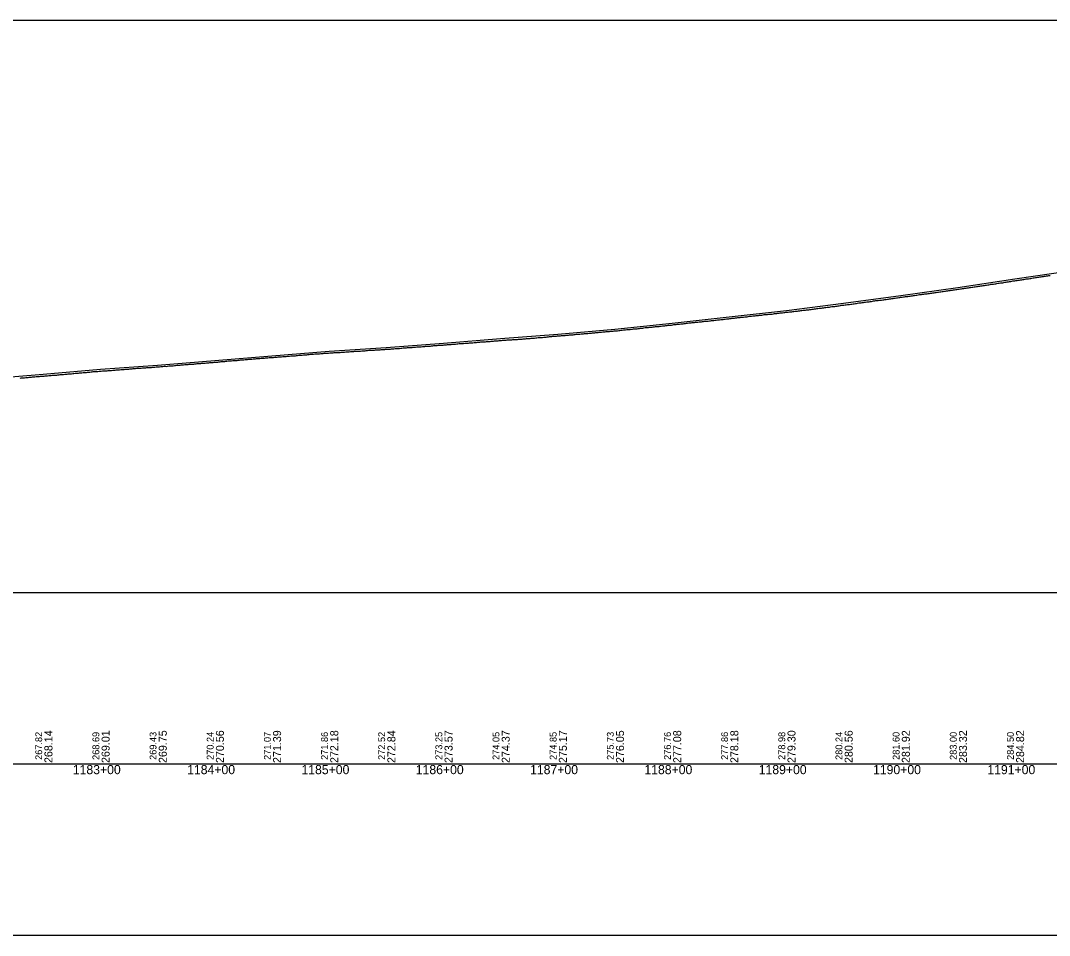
# Model space of a CAD drawing. Extents: x 2898 to 49495, y -15038 to -13538.
# Drawn here: x 7583 to 8483, y -15038 to -14238 of the extents above; entities that cross this region are included whole.
import ezdxf

# ---------------------------------------------------------------- set-up
doc = ezdxf.new("R2010")
doc.units = 0
for name, color, linetype in [('RD_DDB_Profile_EX', 7, 'Continuous'), ('RD_DDB_Profile_PR', 7, 'Continuous'), ('RD_DDB_StaTX', 7, 'Continuous'), ('RD_DDB_StripGrade', 7, 'Continuous'), ('RD_GPK_Profile_Cell', 7, 'Continuous'), ('RD_SHT_ShtClip', 7, 'Continuous')]:
    doc.layers.add(name, color=color, linetype=linetype)

msp = doc.modelspace()

# ---------------------------------------------------------------- linework, layer by layer
at = {"layer": 'RD_DDB_Profile_EX'}
for points in [[(8445.6, -14467.23), (8446.6, -14467), (8447.6, -14466.91), (8448.59, -14466.7), (8449.6, -14466.56), (8450.6, -14466.37), (8451.6, -14466.15), (8452.22, -14466.1), (8453.23, -14466.02), (8454.23, -14465.77), (8455.23, -14465.67), (8456.23, -14465.5), (8457.22, -14465.36), (8458.23, -14465.18), (8459.23, -14465.06), (8460.23, -14464.89), (8461.23, -14464.79), (8462.23, -14464.67), (8463.23, -14464.44), (8464.23, -14464.28), (8465.23, -14464.16), (8466.23, -14464.01), (8467.23, -14463.88), (8468.23, -14463.72), (8469.23, -14463.55), (8470.23, -14463.4), (8471.23, -14463.14), (8472.23, -14463.04), (8473.23, -14462.96), (8474.23, -14462.84), (8475.23, -14462.66), (8476.23, -14462.54), (8477.24, -14462.26), (8478.23, -14462.15), (8479.02, -14462.01), (8480.01, -14461.91), (8481.02, -14461.81), (8482.02, -14461.58), (8483.01, -14461.51), (8484.02, -14461.34)], [(8345.61, -14481.55), (8346.77, -14481.41), (8347.77, -14481.22), (8348.61, -14481.1), (8349.61, -14480.98), (8350.61, -14480.88), (8351.78, -14480.65), (8352.61, -14480.56), (8353.61, -14480.42), (8354.61, -14480.37), (8355.78, -14480.15), (8356.61, -14480.02), (8357.61, -14479.87), (8358.78, -14479.69), (8359.61, -14479.61), (8360.61, -14479.5), (8361.61, -14479.36), (8362.61, -14479.25), (8363.61, -14479.1), (8364.6, -14478.95), (8365.61, -14478.85), (8366.79, -14478.62), (8367.6, -14478.5), (8368.61, -14478.3), (8369.78, -14478.13), (8370.6, -14477.97), (8371.61, -14477.9), (8372.6, -14477.79), (8373.55, -14477.69), (8374.54, -14477.53), (8375.55, -14477.38), (8376.54, -14477.32), (8377.54, -14477.08), (8378.55, -14477.01), (8379.54, -14476.9), (8380.55, -14476.75), (8381.54, -14476.57), (8382.54, -14476.42), (8383.55, -14476.31), (8384.54, -14476.16), (8385.55, -14476.05), (8386.57, -14475.9), (8387.57, -14475.8), (8388.57, -14475.6), (8389.57, -14475.41), (8390.57, -14475.3), (8391.57, -14475.2), (8392.57, -14475.01), (8393.57, -14474.85), (8394.57, -14474.7), (8395.57, -14474.56), (8396.57, -14474.5), (8397.57, -14474.28), (8398.57, -14474.18), (8399.57, -14474.05), (8400.57, -14473.82), (8401.57, -14473.72), (8402.57, -14473.56), (8403.57, -14473.45), (8404.57, -14473.34), (8405.57, -14473.15), (8406.57, -14472.97), (8407.57, -14472.79), (8408.57, -14472.64), (8409.57, -14472.49), (8410.57, -14472.39), (8411.57, -14472.19), (8412.57, -14472.08), (8413.57, -14471.94), (8414.57, -14471.75), (8415.57, -14471.59), (8416.57, -14471.49), (8417.57, -14471.29), (8418.57, -14471.2), (8419.57, -14471.06), (8420.57, -14470.95), (8421.57, -14470.8), (8422.57, -14470.61), (8423.57, -14470.47), (8424.57, -14470.33), (8425.57, -14470.18), (8426.57, -14470.04), (8427.57, -14469.95), (8428.57, -14469.81), (8429.57, -14469.62), (8430.57, -14469.42), (8431.59, -14469.25), (8432.6, -14469.08), (8433.59, -14468.96), (8434.6, -14468.86), (8435.6, -14468.75), (8436.59, -14468.61), (8437.6, -14468.28), (8438.59, -14468.2), (8439.6, -14468.04), (8440.6, -14467.89), (8441.59, -14467.76), (8442.6, -14467.66), (8443.59, -14467.44), (8444.59, -14467.33), (8445.6, -14467.23)], [(8246.04, -14494.32), (8247.04, -14494.18), (8248.04, -14494.12), (8249.04, -14494.02), (8250.04, -14493.96), (8251.04, -14493.87), (8252.04, -14493.77), (8253.04, -14493.58), (8254.04, -14493.48), (8255.04, -14493.37), (8256.04, -14493.27), (8257.04, -14493.22), (8258.04, -14493.12), (8259.05, -14493.01), (8260.04, -14492.82), (8261.04, -14492.63), (8262.04, -14492.62), (8263.04, -14492.57), (8264.04, -14492.38), (8265.04, -14492.23), (8266.04, -14492.08), (8267.05, -14491.98), (8268.04, -14491.83), (8269.04, -14491.78), (8270.04, -14491.63), (8271.04, -14491.53), (8272.05, -14491.42), (8273.04, -14491.28), (8274.04, -14491.13), (8275.05, -14491.02), (8276.04, -14490.83), (8277.04, -14490.69), (8278.04, -14490.59), (8279.04, -14490.53), (8280.04, -14490.34), (8281.04, -14490.24), (8282.04, -14490.09), (8283.05, -14489.99), (8284.04, -14489.88), (8285.04, -14489.73), (8286.04, -14489.59), (8287.04, -14489.48), (8288.05, -14489.33), (8289.04, -14489.18), (8290.04, -14489.03), (8291.05, -14488.94), (8292.04, -14488.82), (8293.04, -14488.63), (8294.03, -14488.53), (8294.71, -14488.42), (8295.71, -14488.36), (8296.72, -14488.18), (8297.71, -14488.12), (8298.72, -14487.87), (8299.71, -14487.82), (8300.71, -14487.67), (8301.72, -14487.47), (8302.71, -14487.36), (8303.72, -14487.22), (8304.71, -14487.16), (8305.72, -14486.92), (8306.72, -14486.77), (8307.71, -14486.7), (8308.72, -14486.6), (8309.71, -14486.41), (8310.72, -14486.31), (8311.72, -14486.16), (8312.72, -14486.05), (8313.72, -14485.95), (8314.71, -14485.75), (8315.72, -14485.56), (8316.72, -14485.42), (8317.72, -14485.35), (8318.72, -14485.21), (8319.72, -14485.1), (8320.72, -14484.95), (8321.72, -14484.81), (8322.72, -14484.7), (8323.72, -14484.54), (8324.72, -14484.39), (8325.72, -14484.29), (8326.73, -14484.24), (8327.72, -14484.01), (8328.73, -14483.76), (8329.72, -14483.66), (8330.72, -14483.56), (8331.73, -14483.37), (8332.72, -14483.25), (8333.73, -14483.1), (8334.72, -14483.01), (8335.73, -14482.9), (8336.73, -14482.83), (8337.72, -14482.63), (8338.73, -14482.58), (8339.61, -14482.4), (8340.61, -14482.27), (8341.77, -14482.08), (8342.61, -14481.99), (8343.61, -14481.85), (8344.77, -14481.71), (8345.61, -14481.55)], [(8146, -14505.35), (8147, -14505.3), (8148.01, -14505.15), (8149, -14505.05), (8150, -14504.91), (8151.01, -14504.81), (8152, -14504.76), (8153, -14504.7), (8154.01, -14504.6), (8155, -14504.31), (8156, -14504.21), (8157.01, -14504.16), (8158, -14504.01), (8159.01, -14503.91), (8160, -14503.81), (8161, -14503.76), (8162.01, -14503.66), (8163, -14503.51), (8164, -14503.46), (8165.01, -14503.31), (8166, -14503.16), (8167, -14503.01), (8168.01, -14502.91), (8169, -14502.81), (8170, -14502.71), (8171.01, -14502.57), (8172, -14502.46), (8173, -14502.36), (8174, -14502.31), (8175, -14502.21), (8176.01, -14502.11), (8177, -14502.01), (8178, -14501.91), (8179.01, -14501.77), (8180, -14501.66), (8181, -14501.47), (8182.01, -14501.42), (8183, -14501.37), (8184, -14501.27), (8185.01, -14501.26), (8186, -14501.11), (8187, -14500.92), (8188.01, -14500.82), (8189, -14500.68), (8190, -14500.62), (8191, -14500.48), (8192, -14500.37), (8193, -14500.28), (8194, -14500.18), (8195, -14500.08), (8196.01, -14499.97), (8197, -14499.83), (8198, -14499.78), (8199.01, -14499.64), (8199.98, -14499.49), (8200.98, -14499.39), (8201.99, -14499.34), (8202.98, -14499.19), (8203.98, -14499.09), (8204.98, -14499.13), (8205.98, -14498.84), (8206.98, -14498.79), (8207.98, -14498.64), (8208.98, -14498.54), (8209.98, -14498.35), (8210.98, -14498.25), (8211.98, -14498.1), (8212.98, -14498), (8213.98, -14497.9), (8215, -14497.84), (8216, -14497.7), (8217, -14497.55), (8218, -14497.45), (8218.99, -14497.4), (8220, -14497.21), (8221, -14497.06), (8221.99, -14496.96), (8223, -14496.86), (8224, -14496.77), (8224.99, -14496.72), (8226, -14496.66), (8226.99, -14496.46), (8227.99, -14496.36), (8229, -14496.22), (8229.99, -14496.12), (8231.07, -14496.06), (8232, -14496.01), (8232.99, -14495.68), (8233.99, -14495.62), (8235, -14495.56), (8235.99, -14495.47), (8236.99, -14495.37), (8237.99, -14495.22), (8238.99, -14495.12), (8239.99, -14495.07), (8240.99, -14495.06), (8241.99, -14494.82), (8243.04, -14494.71), (8244.04, -14494.61), (8245.04, -14494.47), (8246.04, -14494.32)], [(8046.19, -14514.83), (8047.18, -14514.73), (8048.18, -14514.63), (8049.19, -14514.58), (8050.18, -14514.48), (8051.18, -14514.43), (8052.17, -14514.33), (8053.18, -14514.23), (8053.78, -14514.18), (8054.79, -14514.13), (8055.78, -14514.03), (8056.78, -14513.98), (8057.79, -14513.93), (8058.78, -14513.98), (8059.78, -14513.73), (8060.78, -14513.68), (8061.78, -14513.53), (8062.78, -14513.43), (8063.78, -14513.38), (8064.79, -14513.33), (8065.78, -14513.23), (8066.78, -14513.13), (8067.79, -14513.08), (8068.78, -14512.93), (8069.78, -14512.78), (8070.78, -14512.73), (8071.78, -14512.73), (8072.78, -14512.58), (8073.78, -14512.48), (8074.78, -14512.34), (8075.78, -14512.33), (8076.78, -14512.23), (8077.79, -14512.14), (8078.78, -14512.09), (8079.78, -14511.98), (8080.78, -14511.88), (8081.78, -14511.74), (8082.78, -14511.68), (8083.78, -14511.59), (8084.78, -14511.49), (8085.78, -14511.39), (8086.78, -14511.24), (8087.77, -14511.19), (8088.78, -14511.14), (8089.78, -14511.04), (8090.77, -14510.94), (8091.78, -14510.89), (8092.78, -14510.79), (8093.78, -14510.64), (8094.77, -14510.54), (8095.78, -14510.49), (8096.78, -14510.39), (8097.77, -14510.34), (8098.78, -14510.29), (8099.78, -14510.14), (8100.77, -14510.04), (8101.78, -14509.94), (8102.78, -14509.89), (8103.77, -14509.79), (8104.77, -14509.69), (8105.78, -14509.64), (8106.78, -14509.49), (8107.77, -14509.34), (8108.78, -14509.19), (8109.78, -14509.14), (8110.77, -14509.04), (8111.77, -14508.94), (8112.78, -14508.84), (8113.77, -14508.74), (8114.77, -14508.64), (8115.78, -14508.59), (8116.77, -14508.49), (8117.77, -14508.34), (8118.78, -14508.19), (8119.78, -14508.14), (8120.77, -14508.09), (8121.77, -14508.04), (8122.78, -14507.89), (8123.77, -14507.75), (8124.77, -14507.6), (8125.78, -14507.5), (8126.77, -14507.4), (8127.77, -14507.34), (8128.78, -14507.1), (8129.77, -14507), (8130.77, -14506.95), (8131.77, -14506.9), (8132.78, -14506.8), (8134, -14506.6), (8135.01, -14506.5), (8136.02, -14506.5), (8137, -14506.4), (8138.02, -14506.2), (8139.02, -14506.1), (8140.01, -14506), (8141, -14505.95), (8142.01, -14505.85), (8143, -14505.7), (8144, -14505.6), (8145.01, -14505.5), (8146, -14505.35)], [(7946.07, -14522.67), (7947.07, -14522.57), (7948.06, -14522.52), (7949.07, -14522.37), (7950.07, -14522.32), (7951.06, -14522.27), (7952.32, -14522.22), (7953.07, -14522.22), (7954.15, -14522.15), (7955.06, -14522.02), (7956.13, -14521.91), (7957.07, -14521.82), (7958.06, -14521.67), (7959.06, -14521.67), (7960.07, -14521.62), (7961.06, -14521.52), (7962.06, -14521.47), (7963.07, -14521.37), (7964.06, -14521.32), (7965.06, -14521.17), (7966.07, -14521.02), (7967.06, -14520.97), (7968.06, -14520.87), (7969.06, -14520.77), (7970.07, -14520.82), (7971.06, -14520.77), (7972.06, -14520.67), (7973.07, -14520.52), (7974.19, -14520.47), (7975.19, -14520.42), (7976.19, -14520.37), (7977.19, -14520.27), (7978.19, -14520.22), (7979.19, -14520.12), (7980.19, -14520.07), (7981.19, -14519.97), (7982.19, -14519.87), (7983.19, -14519.82), (7984.19, -14519.77), (7985.19, -14519.62), (7986.19, -14519.52), (7987.19, -14519.42), (7988.19, -14519.32), (7989.18, -14519.32), (7990.19, -14519.27), (7991.19, -14519.22), (7992.19, -14519.12), (7993.19, -14519.02), (7994.19, -14518.97), (7995.19, -14518.92), (7996.19, -14518.77), (7997.19, -14518.72), (7998.19, -14518.57), (7999.18, -14518.57), (8000.19, -14518.52), (8001.19, -14518.52), (8002.18, -14518.32), (8003.19, -14518.22), (8004.19, -14518.12), (8005.19, -14518.02), (8006.18, -14518.02), (8007.19, -14517.97), (8008.19, -14517.83), (8009.18, -14517.78), (8010.19, -14517.72), (8011.19, -14517.68), (8012.18, -14517.58), (8013.18, -14517.53), (8014.19, -14517.48), (8015.18, -14517.42), (8016.18, -14517.43), (8017.19, -14517.32), (8018.19, -14517.23), (8019.18, -14517.18), (8020.19, -14517.08), (8021.19, -14516.98), (8022.18, -14516.93), (8023.18, -14516.88), (8024.19, -14516.83), (8025.18, -14516.73), (8026.18, -14516.58), (8027.18, -14516.58), (8028.19, -14516.52), (8029.18, -14516.38), (8030.19, -14516.33), (8031.19, -14516.23), (8032.18, -14516.18), (8033.19, -14516.08), (8034.18, -14516.03), (8035.18, -14515.83), (8036.19, -14515.73), (8037.18, -14515.68), (8038.18, -14515.63), (8039.19, -14515.53), (8040.18, -14515.48), (8041.19, -14515.38), (8042.18, -14515.23), (8043.19, -14515.18), (8044.19, -14515.03), (8045.17, -14514.93), (8046.19, -14514.83)], [(7846.12, -14529.71), (7846.96, -14529.67), (7848.09, -14529.55), (7848.96, -14529.42), (7849.98, -14529.36), (7850.96, -14529.27), (7852.01, -14529.26), (7852.96, -14529.22), (7853.96, -14529.12), (7854.96, -14529.07), (7855.95, -14528.97), (7856.96, -14528.92), (7857.96, -14528.82), (7858.95, -14528.82), (7859.96, -14528.82), (7860.96, -14528.77), (7861.96, -14528.67), (7862.95, -14528.62), (7863.96, -14528.52), (7864.96, -14528.47), (7865.95, -14528.42), (7866.95, -14528.37), (7867.96, -14528.27), (7868.96, -14528.12), (7869.95, -14528.12), (7870.96, -14528.07), (7871.96, -14527.97), (7872.95, -14527.97), (7873.95, -14527.92), (7874.96, -14527.77), (7875.95, -14527.67), (7876.95, -14527.62), (7877.96, -14527.57), (7878.96, -14527.57), (7879.95, -14527.52), (7880.95, -14527.42), (7881.96, -14527.37), (7882.95, -14527.22), (7883.95, -14527.17), (7884.96, -14527.12), (7885.95, -14526.92), (7886.95, -14526.87), (7888.05, -14526.82), (7889.06, -14526.77), (7890.05, -14526.77), (7891.05, -14526.67), (7892.06, -14526.62), (7893.05, -14526.57), (7894.05, -14526.42), (7895.05, -14526.42), (7896.06, -14526.37), (7897.05, -14526.32), (7898.05, -14526.27), (7899.05, -14526.17), (7900.05, -14526.07), (7901.05, -14525.97), (7902.05, -14526.02), (7903.06, -14525.92), (7904.05, -14525.82), (7905.05, -14525.77), (7906.05, -14525.77), (7907.05, -14525.67), (7908.05, -14525.57), (7909.05, -14525.52), (7910.06, -14525.47), (7911.05, -14525.27), (7912.05, -14525.22), (7913.05, -14525.22), (7914.05, -14525.17), (7915.05, -14525.17), (7916.05, -14525.02), (7917.06, -14524.87), (7918.05, -14524.77), (7919.05, -14524.72), (7920.05, -14524.67), (7921.05, -14524.52), (7922.05, -14524.47), (7923.05, -14524.42), (7924.05, -14524.32), (7925.05, -14524.27), (7926.05, -14524.22), (7927.05, -14524.12), (7928.05, -14524.07), (7929.05, -14523.97), (7930.05, -14523.87), (7931.05, -14523.82), (7932.05, -14523.72), (7933.05, -14523.67), (7934.05, -14523.62), (7935.05, -14523.52), (7936.07, -14523.42), (7937.07, -14523.42), (7938.06, -14523.27), (7939.07, -14523.22), (7940.07, -14523.17), (7941.06, -14523.17), (7942.07, -14523.07), (7943.07, -14522.92), (7944.07, -14522.82), (7945.06, -14522.72), (7946.07, -14522.67)], [(7746.07, -14537.8), (7747.07, -14537.65), (7748.07, -14537.64), (7749.07, -14537.55), (7750.07, -14537.49), (7751.07, -14537.44), (7752.07, -14537.44), (7753.07, -14537.29), (7754.07, -14537.2), (7755.06, -14537.14), (7756.07, -14537.04), (7757.07, -14536.8), (7758.07, -14536.75), (7759.07, -14536.7), (7760.07, -14536.55), (7761.07, -14536.54), (7762.06, -14536.45), (7763.07, -14536.3), (7764.07, -14536.29), (7765.07, -14536.15), (7766.07, -14536.05), (7767.07, -14536), (7768.07, -14535.94), (7769.06, -14535.84), (7770.07, -14535.7), (7771.04, -14535.65), (7771.87, -14535.65), (7772.87, -14535.59), (7773.88, -14535.44), (7774.87, -14535.29), (7775.88, -14535.24), (7776.88, -14535.19), (7777.87, -14535.09), (7778.88, -14535.04), (7779.88, -14534.94), (7780.87, -14534.84), (7781.88, -14534.79), (7782.88, -14534.69), (7783.87, -14534.59), (7784.87, -14534.49), (7785.88, -14534.44), (7786.87, -14534.34), (7787.87, -14534.29), (7788.88, -14534.14), (7789.87, -14534.09), (7790.87, -14533.99), (7791.88, -14533.99), (7792.87, -14533.94), (7793.87, -14533.79), (7794.87, -14533.69), (7795.87, -14533.64), (7796.87, -14533.64), (7797.87, -14533.49), (7798.88, -14533.43), (7799.87, -14533.38), (7800.87, -14533.23), (7801.88, -14533.18), (7802.87, -14533.18), (7803.87, -14533.08), (7804.87, -14532.98), (7805.87, -14532.88), (7806.87, -14532.78), (7807.87, -14532.73), (7808.87, -14532.63), (7809.87, -14532.53), (7810.87, -14532.53), (7811.87, -14532.43), (7812.87, -14532.33), (7813.87, -14532.28), (7814.86, -14532.18), (7815.87, -14532.13), (7816.87, -14532.03), (7817.86, -14531.93), (7818.87, -14531.78), (7819.87, -14531.73), (7820.86, -14531.72), (7821.87, -14531.62), (7822.87, -14531.57), (7823.86, -14531.52), (7824.86, -14531.37), (7825.87, -14531.27), (7826.86, -14531.12), (7827.86, -14531.07), (7828.87, -14531.02), (7829.86, -14531.02), (7830.86, -14530.87), (7831.87, -14530.77), (7832.87, -14530.77), (7833.86, -14530.72), (7834.86, -14530.52), (7835.87, -14530.42), (7836.86, -14530.32), (7837.86, -14530.22), (7838.87, -14530.32), (7839.86, -14530.07), (7840.86, -14530.02), (7841.87, -14530.02), (7842.86, -14529.97), (7843.86, -14529.87), (7844.96, -14529.77), (7846.12, -14529.71)], [(7646.11, -14545.54), (7647.1, -14545.44), (7648.11, -14545.44), (7649.11, -14545.29), (7650.1, -14545.24), (7651.1, -14545.19), (7652.11, -14545.09), (7653.1, -14545.04), (7654.1, -14544.99), (7655.11, -14544.89), (7656.11, -14544.84), (7657.1, -14544.79), (7658.1, -14544.78), (7659.11, -14544.78), (7660.1, -14544.49), (7661.1, -14544.44), (7662.11, -14544.39), (7663.11, -14544.34), (7664.1, -14544.24), (7665.1, -14544.19), (7666.11, -14544.14), (7667.1, -14543.99), (7668.1, -14543.84), (7669.1, -14543.79), (7670.11, -14543.74), (7671.1, -14543.69), (7672.1, -14543.59), (7673.11, -14543.49), (7674.1, -14543.44), (7675.1, -14543.34), (7676.1, -14543.29), (7677.1, -14543.24), (7678.1, -14543.19), (7679.1, -14543.09), (7680.1, -14542.99), (7681.1, -14542.94), (7682.1, -14542.84), (7683.1, -14542.74), (7684.1, -14542.64), (7685.1, -14542.54), (7686.1, -14542.49), (7687.1, -14542.44), (7688.06, -14542.39), (7689.06, -14542.34), (7690.06, -14542.24), (7691.06, -14542.14), (7692.06, -14542.09), (7693.06, -14542.04), (7694.06, -14541.94), (7695.06, -14541.89), (7696.07, -14541.79), (7697.07, -14541.74), (7698.08, -14541.69), (7699.07, -14541.59), (7700.07, -14541.59), (7701.07, -14541.44), (7702.07, -14541.39), (7703.07, -14541.34), (7704.07, -14541.24), (7705.07, -14541.14), (7706.07, -14541.09), (7707.07, -14540.99), (7708.07, -14540.89), (7709.07, -14540.79), (7710.07, -14540.79), (7711.07, -14540.84), (7712.07, -14540.55), (7713.07, -14540.45), (7714.07, -14540.34), (7715.07, -14540.29), (7716.07, -14540.29), (7717.07, -14540.24), (7718.07, -14540.19), (7719.07, -14540.04), (7720.07, -14539.94), (7721.07, -14539.89), (7722.07, -14539.85), (7723.07, -14539.69), (7724.07, -14539.64), (7725.07, -14539.59), (7726.07, -14539.49), (7727.07, -14539.3), (7728.07, -14539.29), (7729.07, -14539.19), (7730.06, -14539.09), (7731.07, -14539.04), (7732.07, -14538.99), (7733.07, -14538.89), (7734.07, -14538.84), (7735.07, -14538.79), (7736.07, -14538.69), (7737.06, -14538.59), (7738.07, -14538.4), (7739.07, -14538.35), (7740.07, -14538.3), (7741.07, -14538.2), (7742.07, -14538.15), (7743.07, -14538.1), (7744.07, -14537.94), (7745.07, -14537.94), (7746.07, -14537.8)], [(7583, -14551.03), (7584, -14550.93), (7585.01, -14550.88), (7586, -14550.83), (7587, -14550.73), (7588.01, -14550.68), (7589.01, -14550.58), (7590, -14550.48), (7591.02, -14550.38), (7592.01, -14550.33), (7593, -14550.28), (7594, -14550.13), (7595, -14550.03), (7596, -14549.93), (7597.01, -14549.83), (7598, -14549.78), (7599, -14549.68), (7600, -14549.58), (7601.01, -14549.53), (7602, -14549.48), (7603.01, -14549.38), (7604, -14549.28), (7605, -14549.13), (7606.12, -14549.08), (7607.12, -14548.98), (7608.12, -14548.93), (7609.12, -14548.88), (7610.12, -14548.73), (7611.11, -14548.68), (7612.11, -14548.63), (7613.1, -14548.48), (7614.12, -14548.43), (7615.12, -14548.43), (7616.11, -14548.23), (7617.11, -14548.18), (7618.11, -14548.08), (7619.11, -14547.98), (7620.11, -14547.88), (7621.11, -14547.83), (7622.11, -14547.69), (7623.11, -14547.58), (7624.11, -14547.58), (7625.11, -14547.48), (7626.11, -14547.38), (7627.11, -14547.33), (7628.11, -14547.23), (7629.1, -14547.18), (7630.11, -14547.03), (7631.11, -14546.88), (7632.11, -14546.83), (7633.11, -14546.93), (7634.11, -14546.68), (7635.11, -14546.58), (7636.1, -14546.53), (7637.11, -14546.44), (7638.11, -14546.29), (7639.11, -14546.24), (7640.1, -14546.19), (7641.11, -14546.09), (7642.11, -14545.99), (7643.1, -14545.94), (7644.11, -14545.79), (7645.11, -14545.59), (7646.11, -14545.54)]]:
    msp.add_lwpolyline(points, dxfattribs=at)
at = {"layer": 'RD_DDB_Profile_PR'}
msp.add_lwpolyline([(7553.38, -14551.64), (7603.38, -14547.74), (7653.38, -14543.42), (7703.38, -14539.71), (7753.38, -14535.66), (7803.38, -14531.53), (7853.38, -14527.57), (7903.38, -14524.29), (7953.38, -14520.6), (8003.38, -14516.6), (8053.38, -14512.62), (8103.38, -14508.23), (8153.38, -14503.07), (8203.38, -14497.55), (8253.38, -14491.95), (8303.38, -14485.67), (8353.38, -14478.85), (8403.38, -14471.87), (8453.38, -14464.38), (8503.38, -14456.97)], dxfattribs=at)
at = {"layer": 'RD_GPK_Profile_Cell'}
msp.add_line((2976.05, -14888.47), (48721.13, -14888.47), dxfattribs=at)
at = {"layer": 'RD_SHT_ShtClip'}
for points in [[(8976.22, -14738.47), (8976.22, -14238.47), (8976.22, -14238.47), (7476.38, -14238.47), (7476.38, -14738.47)], [(7456.38, -14738.47), (8996.05, -14738.47), (8996.05, -15038.47), (7456.38, -15038.47)]]:
    msp.add_lwpolyline(points, close=True, dxfattribs=at)

# ---------------------------------------------------------------- texts
at = {"layer": 'RD_DDB_StaTX'}
for s, p in [('1183+00', (7629.18, -14897.47)), ('1184+00', (7729.18, -14897.47)), ('1185+00', (7829.18, -14897.47)), ('1186+00', (7929.18, -14897.47)), ('1187+00', (8029.18, -14897.47)), ('1188+00', (8129.18, -14897.47)), ('1189+00', (8229.18, -14897.47)), ('1190+00', (8329.18, -14897.47)), ('1191+00', (8429.18, -14897.47))]:
    msp.add_text(s, height=8, dxfattribs=at).set_placement(p)
at = {"layer": 'RD_DDB_StripGrade'}
for s, height, p in [('267.82', 6, (7602.38, -14884.98)), ('268.14', 7, (7611.38, -14887.72)), ('268.69', 6, (7652.38, -14884.98)), ('269.01', 7, (7661.38, -14887.72)), ('269.43', 6, (7702.38, -14884.98)), ('269.75', 7, (7711.38, -14887.72)), ('270.24', 6, (7752.38, -14884.98)), ('270.56', 7, (7761.38, -14887.72)), ('271.07', 6, (7802.38, -14884.98)), ('271.39', 7, (7811.38, -14887.72)), ('271.86', 6, (7852.38, -14884.98)), ('272.18', 7, (7861.38, -14887.72)), ('272.52', 6, (7902.38, -14884.98)), ('272.84', 7, (7911.38, -14887.72)), ('273.25', 6, (7952.38, -14884.98)), ('273.57', 7, (7961.38, -14887.72)), ('274.05', 6, (8002.38, -14884.98)), ('274.37', 7, (8011.38, -14887.72)), ('274.85', 6, (8052.38, -14884.98)), ('275.17', 7, (8061.38, -14887.72)), ('275.73', 6, (8102.38, -14884.98)), ('276.05', 7, (8111.38, -14887.72)), ('276.76', 6, (8152.38, -14884.98)), ('277.08', 7, (8161.38, -14887.72)), ('277.86', 6, (8202.38, -14884.98)), ('278.18', 7, (8211.38, -14887.72)), ('278.98', 6, (8252.38, -14884.98)), ('279.30', 7, (8261.38, -14887.72)), ('280.24', 6, (8302.38, -14884.98)), ('280.56', 7, (8311.38, -14887.72)), ('281.60', 6, (8352.38, -14884.98)), ('281.92', 7, (8361.38, -14887.72)), ('283.00', 6, (8402.38, -14884.98)), ('283.32', 7, (8411.38, -14887.72)), ('284.50', 6, (8452.38, -14884.98)), ('284.82', 7, (8461.38, -14887.72))]:
    msp.add_text(s, height=height, rotation=90, dxfattribs=at).set_placement(p)

doc.saveas('drawing.dxf')
